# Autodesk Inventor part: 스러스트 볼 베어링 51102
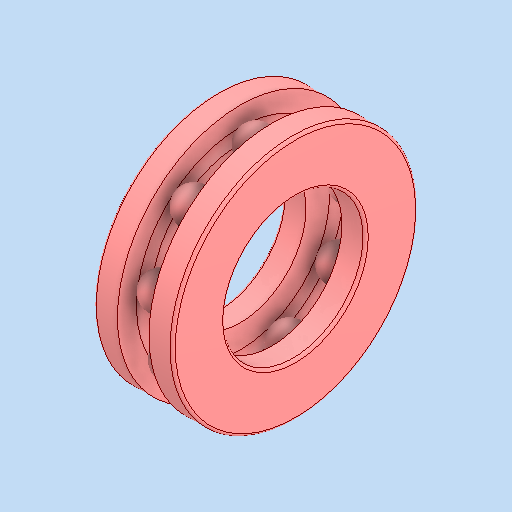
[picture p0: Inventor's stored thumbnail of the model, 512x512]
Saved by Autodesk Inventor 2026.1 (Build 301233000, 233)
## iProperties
Created: 2025-09
Part Number: 스러스트 볼 베어링 51102
Material: 강철, 연강
Description: 롤링 베어링 - 플랫 뒷면이 있는 스러스트 볼 베어링
Document SubType Name: Modeling
Designer: PC-30
Density: 7.85 g/cm^3
Appearance: 기본값
Author: jhkim
Sending System: Autodesk Inventor 2026
Preprocessor: ST-DEVELOPER v20.1
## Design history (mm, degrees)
feature "Solid1"
feature "Solid1:1"
feature "Solid1:2"
feature "Solid1:3"
feature "Solid1:4"
feature "Solid1:5"
feature "Solid1:6"
feature "Solid1:7"
feature "Solid1:8"
feature "Solid1:9"
feature "Solid1:10"
node "솔리드1"
node "솔리드2"
node "솔리드3"
node "솔리드4"
node "솔리드5"
node "솔리드6"
node "솔리드7"
node "솔리드8"
node "솔리드9"
node "솔리드10"
node "솔리드11"
